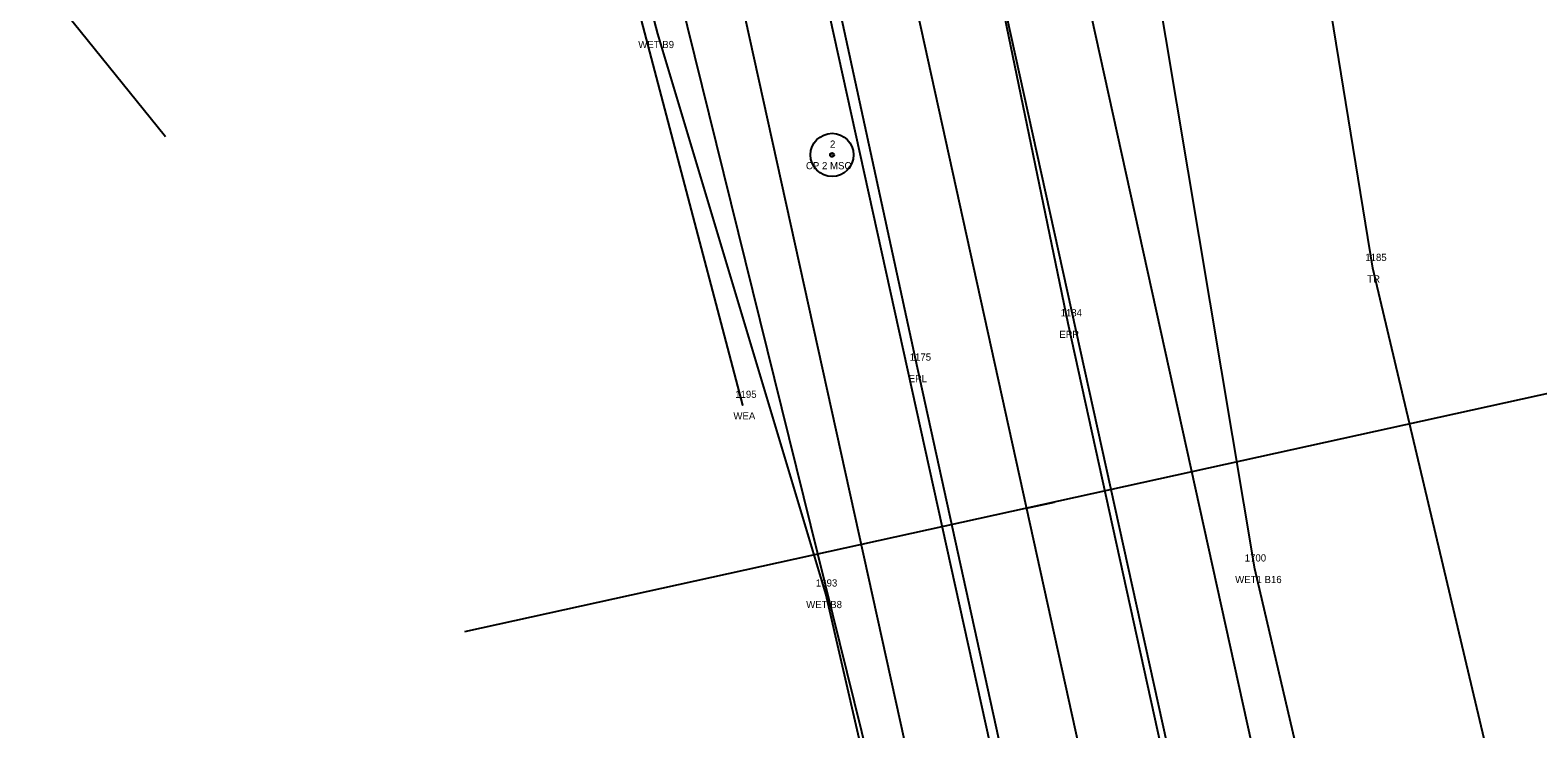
# Model space of a CAD drawing. Extents: x 2522090 to 2524658, y 882711 to 887512.
# Drawn here: x 2523693.6 to 2523903.3, y 884896.1 to 884993.3 of the extents above; entities that cross this region are included whole.
import ezdxf

# ---------------------------------------------------------------- set-up
doc = ezdxf.new("R2010")
doc.units = 0
for name, color, linetype in [('RD_EV_JurisArea', 7, 'Continuous'), ('RD_EX_H2O', 7, 'Continuous'), ('RD_EX_H2O_txCode', 7, 'Continuous'), ('RD_EX_H2O_WetLd_txCode', 7, 'Continuous'), ('RD_EX_Road', 7, 'Continuous'), ('RD_EX_Road_txCode', 7, 'Continuous'), ('RD_EX_VEG', 7, 'Continuous'), ('RD_EX_VEG_txCode', 7, 'Continuous'), ('RD_HC_Cl', 7, 'Continuous'), ('RD_HC_Data', 7, 'Continuous'), ('RD_HC_Data_Tic', 7, 'Continuous'), ('RD_HC_txCode', 7, 'Continuous'), ('RD_PD_Final_TrvlWay', 7, 'Continuous'), ('RD_PD_GR', 7, 'Continuous'), ('RD_PD_PatLn5', 7, 'Continuous'), ('RD_PD_PatLn6', 7, 'Continuous'), ('RD_SMD_Locator', 7, 'Continuous')]:
    doc.layers.add(name, color=color, linetype=linetype)

msp = doc.modelspace()

# ---------------------------------------------------------------- linework, layer by layer
at = {"layer": 'RD_EV_JurisArea'}
for points in [[(2523944.86, 884550.08), (2523910.41, 884709.58), (2523888.01, 884815.03), (2523863.93, 884918.37), (2523848.43, 885010.84), (2523837.07, 885095.13), (2523817.82, 885104.47)], [(2523827.75, 884469.64), (2523867.43, 884517.67), (2523885.95, 884534.84), (2523882.77, 884582.72), (2523847.74, 884736.42), (2523822.93, 884833.79), (2523804.26, 884914.89), (2523780.91, 884992.76), (2523770.73, 885031.48), (2523760.5, 885068.9)]]:
    msp.add_lwpolyline(points, dxfattribs=at)
at = {"layer": 'RD_EX_H2O'}
msp.add_lwpolyline([(2523792.73, 884941.12), (2523763.67, 885051.56), (2523756.26, 885062.72), (2523770.47, 885094.55), (2523817.57, 885105.71), (2523827.83, 885106)], dxfattribs=at)
at = {"layer": 'RD_EX_Road'}
for p, q in [((2523837.97, 884952.46), (2523817.58, 885050.92)), ((2523817, 884946.3), (2523795.47, 885045.91)), ((2523858.56, 884858.71), (2523837.97, 884952.46)), ((2523837.34, 884853.78), (2523817, 884946.3))]:
    msp.add_line(p, q, dxfattribs=at)
at = {"layer": 'RD_EX_VEG'}
for points in [[(2523800.23, 884418.22), (2523892.24, 884498.97), (2523844.57, 884752.81), (2523771.94, 885046.88), (2523769.06, 885076.62)], [(2523998.75, 884575.96), (2523966.17, 884559.06), (2523924.93, 884771.45), (2523880.33, 884960.16), (2523862.36, 885070.56)]]:
    msp.add_lwpolyline(points, dxfattribs=at)
at = {"layer": 'RD_HC_Cl'}
msp.add_line((2523641.17, 885794.2), (2524197.76, 883266.56), dxfattribs=at)
at = {"layer": 'RD_HC_Data'}
for radius in [3, 0.282]:
    msp.add_circle((2523805.14, 884975.91), radius, dxfattribs=at)
at = {"layer": 'RD_HC_Data_Tic'}
msp.add_line((2523832.17, 884926.78), (2523836.08, 884927.64), dxfattribs=at)
at = {"layer": 'RD_PD_Final_TrvlWay'}
for p, q in [((2523722.39, 885481.14), (2524037.44, 884050.42)), ((2523698.95, 885475.98), (2524014, 884045.26))]:
    msp.add_line(p, q, dxfattribs=at)
at = {"layer": 'RD_PD_GR'}
for p, q in [((2523833.35, 885030.72), (2523900.02, 884727.97)), ((2523854.12, 884717.86), (2523787.45, 885020.61))]:
    msp.add_line(p, q, dxfattribs=at)
at = {"layer": 'RD_PD_PatLn5'}
msp.add_line((2523910.3, 884943.98), (2523754.05, 884909.58), dxfattribs=at)
at = {"layer": 'RD_PD_PatLn6'}
msp.add_line((2523612.04, 885103.02), (2523712.47, 884978.46), dxfattribs=at)
at = {"layer": 'RD_SMD_Locator'}
for centre in [(2523780.91, 884992.76), (2523805.14, 884975.91), (2523880.33, 884960.16), (2523837.97, 884952.46), (2523817, 884946.3), (2523792.73, 884941.12), (2523863.93, 884918.37), (2523804.26, 884914.89)]:
    msp.add_circle(centre, 0.001, dxfattribs=at)

# ---------------------------------------------------------------- texts
at = {"layer": 'RD_EX_H2O_txCode'}
for s, p in [('1195', (2523791.67, 884942.12)), ('WEA', (2523791.42, 884939.12))]:
    msp.add_text(s, height=1, dxfattribs=at).set_placement(p)
at = {"layer": 'RD_EX_H2O_WetLd_txCode'}
for s, p in [('WET B9', (2523778.19, 884990.76)), ('1700', (2523862.51, 884919.37)), ('1693', (2523802.89, 884915.89)), ('WET1 B16', (2523861.18, 884916.37)), ('WET B8', (2523801.54, 884912.89))]:
    msp.add_text(s, height=1, dxfattribs=at).set_placement(p)
at = {"layer": 'RD_EX_Road_txCode'}
for s, p in [('1184', (2523836.91, 884953.46)), ('EPR', (2523836.74, 884950.46)), ('1175', (2523815.93, 884947.3)), ('EPL', (2523815.79, 884944.3))]:
    msp.add_text(s, height=1, dxfattribs=at).set_placement(p)
at = {"layer": 'RD_EX_VEG_txCode'}
for s, p in [('1185', (2523879.27, 884961.16)), ('TR', (2523879.54, 884958.16))]:
    msp.add_text(s, height=1, dxfattribs=at).set_placement(p)
at = {"layer": 'RD_HC_txCode'}
for s, p in [('2', (2523804.85, 884976.91)), ('CP 2 MSC', (2523801.51, 884973.91))]:
    msp.add_text(s, height=1, dxfattribs=at).set_placement(p)

doc.saveas('drawing.dxf')
